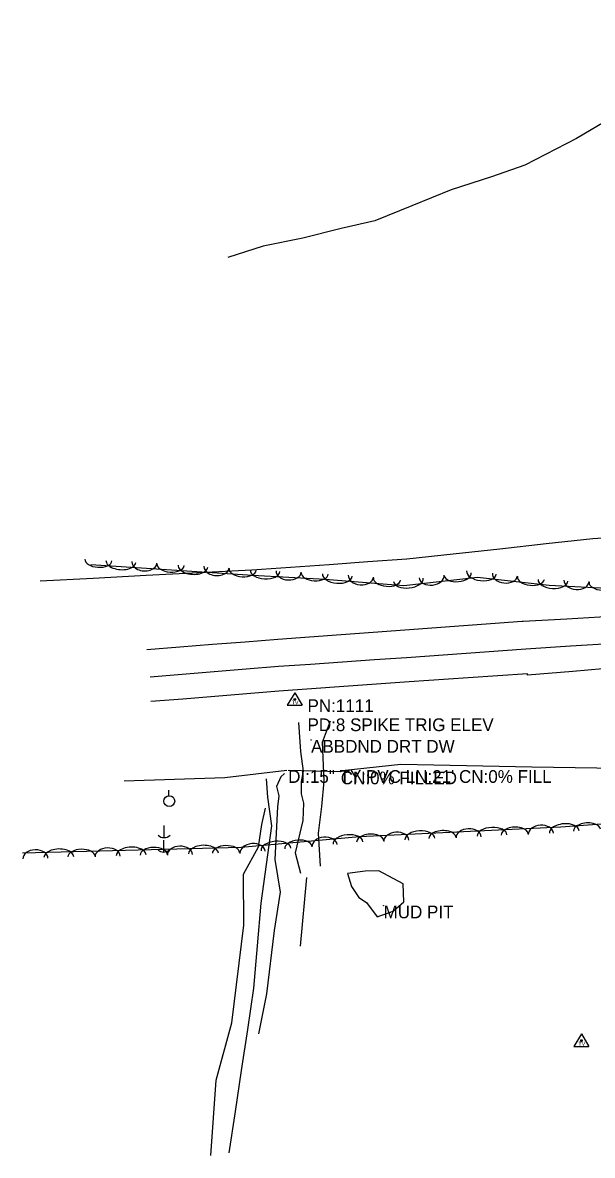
# Model space of a CAD drawing. Extents: x 1451369 to 1458940, y 1868647 to 1875095.
# Drawn here: x 1453227.7 to 1453451.7, y 1870891.7 to 1871337.1 of the extents above; entities that cross this region are included whole.
import ezdxf

# ---------------------------------------------------------------- set-up
doc = ezdxf.new("R2010")
doc.units = 0
for name, color, linetype in [('E_Const Align', 7, 'Continuous'), ('E_PL and Hook', 7, 'Continuous'), ('E_Proposed ROW and Easements', 7, 'Continuous'), ('E_ROW Point Number', 7, 'Continuous'), ('E_Station Offset', 7, 'Continuous'), ('E_Tract Number', 7, 'Continuous'), ('E_Tract Residual', 7, 'Continuous'), ('S_DRIVEWAY', 7, 'Continuous'), ('S_EDGE_PAVEMENT', 7, 'Continuous'), ('S_EXIST_ROW', 7, 'Continuous'), ('S_PAVEMENT_CROWN', 7, 'Continuous'), ('S_SECONDARY_CTL_ANNOT', 7, 'Continuous'), ('S_SIDE_DRAIN_ANNOT', 7, 'Continuous'), ('S_SURVEY_TEXT_ANNOT', 7, 'Continuous'), ('S_TRAILS', 7, 'Continuous')]:
    doc.layers.add(name, color=color, linetype=linetype)

msp = doc.modelspace()

# ---------------------------------------------------------------- linework, layer by layer
at = {"layer": 'E_Const Align'}
for p, q in [((1453285.24, 1871033.11), (1453285.24, 1871035.22)), ((1453283.25, 1871021.32), (1453283.25, 1871016.59)), ((1453283.09, 1871015.66), (1453283.09, 1871010.93))]:
    msp.add_line(p, q, dxfattribs=at)
msp.add_circle((1453285.36, 1871030.97), 2.13, dxfattribs=at)
for centre in [(1453283.31, 1871020.02), (1453283.15, 1871014.36)]:
    msp.add_arc(centre, 3.41, 226.3972, 313.6028, dxfattribs=at)
at = {"layer": 'E_PL and Hook'}
msp.add_line((1453332.11, 1871043.15), (1453352.81, 1871042.59), dxfattribs=at)
at = {"layer": 'E_Proposed ROW and Easements'}
for points in [[(1453341.13, 1871055.02), (1453341.13, 1871055.07), (1453341.13, 1871055.02), (1453341.08, 1871055.02), (1453341.13, 1871055.02), (1453341.13, 1871054.97), (1453341.13, 1871055.02), (1453341.18, 1871055.02)], [(1453369.65, 1870989.89), (1453369.65, 1870989.94), (1453369.65, 1870989.89), (1453369.6, 1870989.89), (1453369.65, 1870989.89), (1453369.65, 1870989.84), (1453369.65, 1870989.89), (1453369.7, 1870989.89)]]:
    msp.add_lwpolyline(points, dxfattribs=at)
at = {"layer": 'E_ROW Point Number'}
for points in [[(1454039.82, 1871337.12), (1453992.45, 1871296.2), (1453976.82, 1871280.78), (1453960.32, 1871268.68), (1453922.85, 1871243.35), (1453886.25, 1871218.61), (1453839.09, 1871189.03), (1453787.52, 1871164.25), (1453741.45, 1871151.98), (1453664.24, 1871140.16), (1453599.61, 1871130.45), (1453561.1, 1871125.93), (1453518.5, 1871126.32), (1453491.52, 1871121.48), (1453464.98, 1871114.18), (1453434.82, 1871115.78), (1453406.63, 1871118.92), (1453377.62, 1871115.67), (1453346.72, 1871118.15), (1453318.09, 1871119.73), (1453254.46, 1871123.88)], [(1453227.7, 1871010.68), (1453313.58, 1871012.86), (1453360.11, 1871017.03), (1453439.31, 1871020.86), (1453498.37, 1871025.17), (1453554.25, 1871028.97), (1453592.3, 1871033.98), (1453641.4, 1871044.5), (1453718.76, 1871061.66), (1453776, 1871072.6), (1453831.69, 1871099.59), (1453853.3, 1871112.04), (1453871.84, 1871109.31), (1453897.32, 1871071.61), (1453935.46, 1870997.61), (1453909.48, 1870975.45), (1453911.54, 1870954.62), (1453910.44, 1870939.28), (1453890.79, 1870936.46), (1453902.73, 1870921.25), (1453921.42, 1870905.04)]]:
    msp.add_lwpolyline(points, dxfattribs=at)
for centre, major_axis, ratio, start_param, end_param in [((1453257.48, 1871125.81), (5.33, -0.35), 0.540825, 3.141475, 6.283067), ((1453266.32, 1871125.23), (5.85, -0.38), 0.550208, 3.141471, 6.283064), ((1453275.58, 1871124.89), (4.94, -0.32), 0.68547, 3.141393, 6.282986), ((1453285.84, 1871123.96), (5.33, -0.35), 0.540825, 3.141475, 6.283067), ((1453294.68, 1871123.38), (5.85, -0.38), 0.550208, 3.141471, 6.283064), ((1453303.94, 1871123.04), (4.94, -0.32), 0.68547, 3.141393, 6.282986), ((1453314.2, 1871122.11), (5.33, -0.35), 0.540825, 3.141475, 6.283067), ((1453323.03, 1871121.58), (5.86, -0.32), 0.550067, 3.141593, 6.283185), ((1453332.29, 1871121.33), (4.95, -0.27), 0.685295, 3.141593, 6.283185), ((1453342.56, 1871120.51), (5.34, -0.29), 0.540687, 3.141593, 6.283185), ((1453351.46, 1871119.9), (5.85, -0.47), 0.550067, 3.141593, 6.283185), ((1453360.71, 1871119.42), (4.94, -0.4), 0.685295, 3.141593, 6.283185), ((1453370.96, 1871118.33), (5.33, -0.43), 0.540687, 3.141593, 6.283185), ((1453379.38, 1871118), (5.83, 0.65), 0.550069, 3.141593, 6.283185), ((1453388.55, 1871119.29), (4.92, 0.55), 0.685297, 3.141593, 6.283185), ((1453398.82, 1871120.18), (5.31, 0.6), 0.540688, 3.141593, 6.283185), ((1453408.11, 1871120.89), (5.83, -0.65), 0.550067, 3.141593, 6.283185), ((1453417.34, 1871120.13), (4.92, -0.55), 0.685294, 3.141593, 6.283185), ((1453427.55, 1871118.73), (5.31, -0.59), 0.540686, 3.141593, 6.283185), ((1453436.24, 1871117.83), (5.86, -0.31), 0.550067, 3.141593, 6.283185), ((1453445.5, 1871117.6), (4.95, -0.26), 0.685295, 3.141593, 6.283185), ((1453455.78, 1871116.79), (5.34, -0.28), 0.540687, 3.141593, 6.283185), ((1453403.08, 1871016.72), (-4.95, -0.24), 0.685312, 3.141606, 6.283198), ((1453412.31, 1871017.43), (-5.86, -0.28), 0.55008, 3.141601, 6.283193), ((1453421.17, 1871017.86), (-5.34, -0.26), 0.5407, 3.1416, 6.283193), ((1453431.47, 1871018.1), (-4.95, -0.24), 0.685312, 3.141606, 6.283198), ((1453440.76, 1871018.84), (-5.85, -0.43), 0.550162, 3.141632, 6.283225), ((1453449.6, 1871019.49), (-5.33, -0.39), 0.54078, 3.141631, 6.283224), ((1453336.14, 1871012.75), (-5.33, -0.48), 0.540697, 3.141593, 6.283185), ((1453346.42, 1871013.41), (-4.94, -0.44), 0.685308, 3.141593, 6.283185), ((1453355.62, 1871014.5), (-5.85, -0.52), 0.550078, 3.141593, 6.283185), ((1453364.38, 1871015.11), (-5.34, -0.26), 0.5407, 3.1416, 6.283193), ((1453374.68, 1871015.35), (-4.95, -0.24), 0.685312, 3.141606, 6.283198), ((1453383.92, 1871016.06), (-5.86, -0.28), 0.55008, 3.141601, 6.283193), ((1453392.77, 1871016.49), (-5.34, -0.26), 0.5407, 3.1416, 6.283193), ((1453232.71, 1871008.43), (-4.95, -0.13), 0.685314, 3.14161, 6.283202), ((1453241.96, 1871008.92), (-5.87, -0.15), 0.550082, 3.141603, 6.283196), ((1453250.83, 1871009.15), (-5.34, -0.14), 0.540702, 3.141603, 6.283195), ((1453261.13, 1871009.15), (-4.95, -0.13), 0.685314, 3.14161, 6.283202), ((1453270.38, 1871009.64), (-5.87, -0.15), 0.550082, 3.141603, 6.283196), ((1453279.25, 1871009.87), (-5.34, -0.14), 0.540702, 3.141603, 6.283195), ((1453289.55, 1871009.87), (-4.95, -0.13), 0.685314, 3.14161, 6.283202), ((1453298.8, 1871010.36), (-5.87, -0.15), 0.550082, 3.141603, 6.283196), ((1453307.67, 1871010.59), (-5.34, -0.14), 0.540702, 3.141603, 6.283195), ((1453318.11, 1871010.87), (-4.94, -0.44), 0.685308, 3.141593, 6.283185), ((1453327.31, 1871011.96), (-5.85, -0.52), 0.550078, 3.141593, 6.283185)]:
    msp.add_ellipse(centre, major_axis=major_axis, ratio=ratio, start_param=start_param, end_param=end_param, dxfattribs=at)
at = {"layer": 'E_Station Offset'}
for p, q in [((1453334.72, 1871073.61), (1453331.71, 1871068.65)), ((1453334.72, 1871073.61), (1453337.67, 1871068.65)), ((1453331.71, 1871068.65), (1453337.67, 1871068.65)), ((1453447.47, 1870939.43), (1453444.46, 1870934.48)), ((1453447.47, 1870939.43), (1453450.42, 1870934.48)), ((1453444.46, 1870934.48), (1453450.42, 1870934.48))]:
    msp.add_line(p, q, dxfattribs=at)
for centre, radius in [((1453334.72, 1871071), 0.311), ((1453334.72, 1871071), 0.183), ((1453334.72, 1871071), 0.103), ((1453447.47, 1870936.82), 0.311), ((1453447.47, 1870936.82), 0.183), ((1453447.47, 1870936.82), 0.103)]:
    msp.add_circle(centre, radius, dxfattribs=at)
at = {"layer": 'E_Tract Number'}
for points in [[(1453332.11, 1871043.15), (1453332.11, 1871043.2), (1453332.11, 1871043.15), (1453332.06, 1871043.15), (1453332.11, 1871043.15), (1453332.11, 1871043.1), (1453332.11, 1871043.15), (1453332.16, 1871043.15)], [(1453352.81, 1871042.59), (1453352.81, 1871042.64), (1453352.81, 1871042.59), (1453352.76, 1871042.59), (1453352.81, 1871042.59), (1453352.81, 1871042.54), (1453352.81, 1871042.59), (1453352.86, 1871042.59)]]:
    msp.add_lwpolyline(points, dxfattribs=at)
at = {"layer": 'E_Tract Residual'}
for points in [[(1453459.28, 1871299.74), (1453445.55, 1871291.53), (1453425.2, 1871281.13), (1453412.07, 1871276.52), (1453396.17, 1871271.36), (1453380.75, 1871265.02), (1453366.2, 1871259.21), (1453352.97, 1871256.11), (1453337.84, 1871252.33), (1453322.26, 1871249.17), (1453308.42, 1871244.82)], [(1453330.7, 1871041.78), (1453329.27, 1871040.5), (1453327.51, 1871036.75), (1453328.41, 1871033.09), (1453327.91, 1871028.78), (1453326.93, 1871007.99), (1453329, 1870995.23), (1453326.56, 1870980.13), (1453323.57, 1870955.23), (1453320.5, 1870939.43)], [(1453301.74, 1870891.67), (1453303.83, 1870921.26), (1453309.99, 1870943.73), (1453314.66, 1870982.23), (1453314.6, 1871002.24), (1453320.43, 1871013.06), (1453321.77, 1871021.72), (1453323.21, 1871028.22)]]:
    msp.add_lwpolyline(points, dxfattribs=at)
msp.add_lwpolyline([(1453355.43, 1871002.56), (1453357.07, 1870997.38), (1453359.91, 1870993.13), (1453362.87, 1870991.09), (1453367.07, 1870985.53), (1453373.42, 1870987.63), (1453377.63, 1870991.34), (1453377.4, 1870998.42), (1453367.72, 1871003.58), (1453362.45, 1871003.43)], close=True, dxfattribs=at)
at = {"layer": 'S_DRIVEWAY'}
for points in [[(1453336.19, 1871061.89), (1453337.02, 1871050.47), (1453338.02, 1871042.78), (1453337.21, 1871038.75), (1453337.23, 1871033.8), (1453338.09, 1871030.14), (1453337.85, 1871023.41), (1453334.81, 1871010.59), (1453336.91, 1871002.64)], [(1453344.85, 1871005.42), (1453344.03, 1871018.34), (1453345.32, 1871028.86), (1453346.23, 1871038.87), (1453345.96, 1871045.01), (1453345.59, 1871054.12), (1453348.79, 1871062.57)]]:
    msp.add_lwpolyline(points, dxfattribs=at)
at = {"layer": 'S_EDGE_PAVEMENT'}
for points in [[(1453516.76, 1871109.25), (1453514.06, 1871108.59), (1453511.89, 1871108.05), (1453507.1, 1871107.59), (1453500.92, 1871106.65), (1453479.96, 1871105.09), (1453458.99, 1871103.52), (1453441.73, 1871102.54), (1453424.48, 1871101.57), (1453424.17, 1871101.65), (1453401.1, 1871099.91), (1453378.02, 1871098.17), (1453365.52, 1871097.26), (1453353.01, 1871096.35), (1453340.51, 1871095.43), (1453328, 1871094.52), (1453315.15, 1871093.52), (1453302.3, 1871092.52), (1453289.45, 1871091.52), (1453276.6, 1871090.52)], [(1453517.83, 1871086.64), (1453514.52, 1871086.48), (1453511.59, 1871086.48), (1453509.8, 1871086.63), (1453485.77, 1871085.05), (1453461.74, 1871083.48), (1453444.02, 1871081.98), (1453426.3, 1871080.48), (1453426.25, 1871081.01), (1453402.95, 1871079.42), (1453379.65, 1871077.82), (1453366.86, 1871076.91), (1453354.06, 1871075.99), (1453341.27, 1871075.08), (1453328.48, 1871074.16), (1453315.89, 1871073.15), (1453303.31, 1871072.14), (1453290.72, 1871071.13), (1453278.14, 1871070.11)]]:
    msp.add_lwpolyline(points, dxfattribs=at)
at = {"layer": 'S_EXIST_ROW'}
for points in [[(1453234.64, 1871117.61), (1453255.43, 1871118.69), (1453276.22, 1871119.77), (1453297.02, 1871120.84), (1453317.81, 1871121.92), (1453333.04, 1871123), (1453348.27, 1871124.09), (1453363.5, 1871125.17), (1453378.73, 1871126.25), (1453397.03, 1871128.25), (1453415.33, 1871130.24), (1453433.63, 1871132.24), (1453451.93, 1871134.23), (1453471.53, 1871135.57), (1453491.13, 1871136.9), (1453508.21, 1871139.22), (1453515.88, 1871138.37)], [(1453353.34, 1871042.99), (1453376.48, 1871045.45), (1453389.36, 1871045.2), (1453402.24, 1871044.95), (1453415.11, 1871044.69), (1453427.99, 1871044.44), (1453444.99, 1871044.21), (1453461.99, 1871043.99), (1453478.71, 1871044.62), (1453495.43, 1871045.25), (1453499.7, 1871044.86), (1453505.3, 1871046.74), (1453523.93, 1871047.07), (1453530.6, 1871047.92)], [(1453267.67, 1871038.91), (1453287.45, 1871039.61), (1453307.23, 1871040.31), (1453331.61, 1871043.08)], [(1453323.45, 1871039.71), (1453323.95, 1871032.51), (1453325.61, 1871021.26), (1453323.47, 1871006.03), (1453321.33, 1870990.81), (1453319.91, 1870974.09), (1453318.5, 1870957.38), (1453316.08, 1870941.21), (1453313.66, 1870925.03), (1453311.24, 1870908.85), (1453308.82, 1870892.68)]]:
    msp.add_lwpolyline(points, dxfattribs=at)
at = {"layer": 'S_PAVEMENT_CROWN'}
msp.add_lwpolyline([(1453516.6, 1871096.69), (1453508.81, 1871096.3), (1453506.4, 1871096.05), (1453483.5, 1871094.52), (1453460.6, 1871092.98), (1453443.09, 1871091.87), (1453425.57, 1871090.77), (1453402.13, 1871089.07), (1453378.68, 1871087.38), (1453366.08, 1871086.5), (1453353.48, 1871085.63), (1453340.88, 1871084.75), (1453328.29, 1871083.88), (1453315.66, 1871082.83), (1453303.04, 1871081.78), (1453290.41, 1871080.74), (1453277.79, 1871079.69)], dxfattribs=at)
at = {"layer": 'S_TRAILS'}
msp.add_lwpolyline([(1453339.35, 1871000.94), (1453336.84, 1870973.97)], dxfattribs=at)

# ---------------------------------------------------------------- texts
at = {"layer": 'E_Station Offset'}
for p in [(1453333.52, 1871068.99), (1453446.27, 1870934.81)]:
    msp.add_text('TV', height=1.5, rotation=360, dxfattribs=at).set_placement(p)
at = {"layer": 'S_SECONDARY_CTL_ANNOT'}
for s, p in [('PN:1111', (1453339.72, 1871066)), ('PD:8 SPIKE TRIG ELEV', (1453339.72, 1871058.5))]:
    msp.add_text(s, height=5, dxfattribs=at).set_placement(p)
at = {"layer": 'S_SIDE_DRAIN_ANNOT'}
for s, p in [('DI:15" TY:PVC LN:21\' CN:0% FILL', (1453332.11, 1871038.15)), ('CN:0% FILLED', (1453352.81, 1871037.59))]:
    msp.add_text(s, height=5, dxfattribs=at).set_placement(p)
at = {"layer": 'S_SURVEY_TEXT_ANNOT'}
for s, p in [('ABBDND DRT DW', (1453341.13, 1871050.02)), ('MUD PIT', (1453369.65, 1870984.89))]:
    msp.add_text(s, height=5, dxfattribs=at).set_placement(p)

doc.saveas('drawing.dxf')
